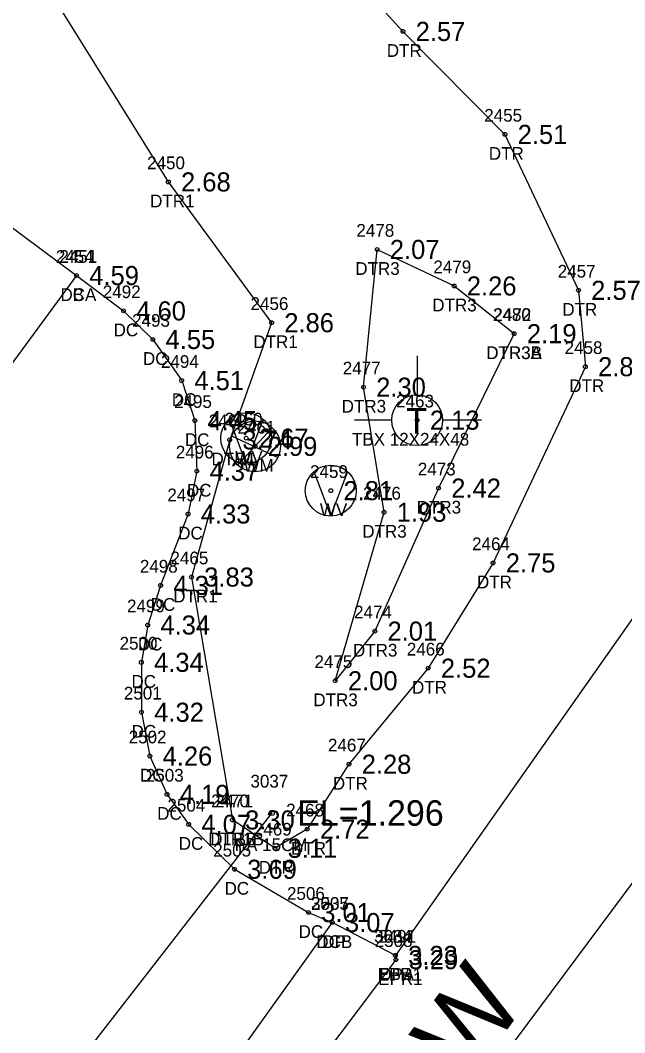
# Model space of a CAD drawing. Extents: x 2608598 to 2610682, y 641451 to 643526.
# Drawn here: x 2610013.4 to 2610061, y 642071.3 to 642151 of the extents above; entities that cross this region are included whole.
import ezdxf

# ---------------------------------------------------------------- set-up
doc = ezdxf.new("R2010")
doc.units = 0
for name, color, linetype in [('RD_EX_Bldg', 7, 'Continuous'), ('RD_EX_Bldg_txCode', 7, 'Continuous'), ('RD_EX_Conc', 7, 'Continuous'), ('RD_EX_Conc_txCode', 7, 'Continuous'), ('RD_EX_DR_Pipe', 7, 'Continuous'), ('RD_EX_DR_Pipe_txCode', 7, 'Continuous'), ('RD_EX_Driveway', 7, 'Continuous'), ('RD_EX_Driveway_txCode', 7, 'Continuous'), ('RD_EX_H2O', 7, 'Continuous'), ('RD_EX_H2O_txCode', 7, 'Continuous'), ('RD_EX_Road', 7, 'Continuous'), ('RD_EX_Road_txCode', 7, 'Continuous'), ('RD_EX_TX_Bldg_ELEV', 7, 'Continuous'), ('RD_EX_TX_Conc_ELEV', 7, 'Continuous'), ('RD_EX_TX_Driveway_ELEV', 7, 'Continuous'), ('RD_EX_TX_H2O_ELEV', 7, 'Continuous'), ('RD_EX_TX_Road_ELEV', 7, 'Continuous'), ('RD_EX_TX_UT_ELEV', 7, 'Continuous'), ('RD_EX_UT', 7, 'Continuous'), ('RD_EX_UT_txCode', 7, 'Continuous'), ('RD_HC_Cl', 7, 'Continuous'), ('RD_HC_Data', 7, 'Continuous'), ('RD_SMD_Locator', 7, 'Continuous'), ('RD_TX_Pipe_ElevEX', 7, 'Continuous')]:
    doc.layers.add(name, color=color, linetype=linetype)

msp = doc.modelspace()

# ---------------------------------------------------------------- linework, layer by layer
at = {"layer": 'RD_EX_Bldg'}
msp.add_lwpolyline([(2609946.85, 642146.346), (2609965.057, 642170.243), (2610017.876, 642130.878), (2610000.016, 642106.607), (2609946.85, 642146.346)], dxfattribs=at)
at = {"layer": 'RD_EX_Conc'}
msp.add_lwpolyline([(2610017.876, 642130.878), (2610021.568, 642128.103), (2610023.872, 642125.855), (2610026.14, 642122.62), (2610027.17, 642119.471), (2610027.332, 642115.497), (2610026.643, 642112.13), (2610024.484, 642106.517), (2610023.47, 642103.398), (2610022.969, 642100.465), (2610022.98, 642096.539), (2610023.642, 642093.093), (2610024.991, 642090.082), (2610026.69, 642087.723), (2610030.29, 642084.192), (2610036.112, 642080.789), (2610037.979, 642080.001)], dxfattribs=at)
at = {"layer": 'RD_EX_DR_Pipe'}
msp.add_line((2610033.217, 642088.618), (2610007.781, 642055.878), dxfattribs=at)
at = {"layer": 'RD_EX_Driveway'}
msp.add_lwpolyline([(2610042.94, 642077.419), (2610037.979, 642080.001), (2610027.537, 642065.432), (2610017.895, 642052.738), (2610020.807, 642047.622)], dxfattribs=at)
at = {"layer": 'RD_EX_H2O'}
for points in [[(2610001.65, 642196.002), (2609997.03, 642194.999), (2609993.92, 642192.054), (2609993.228, 642189.364), (2610025.09, 642138.242), (2610033.208, 642127.171), (2610029.914, 642117.957), (2610026.911, 642107.171), (2610030.124, 642088.07)], [(2610001.65, 642196.002), (2610043.535, 642150.077), (2610051.557, 642141.98), (2610057.335, 642129.719), (2610057.877, 642123.713), (2610050.622, 642108.282), (2610045.517, 642100.001), (2610039.292, 642092.453), (2610036.006, 642087.343), (2610033.47, 642085.842), (2610030.124, 642088.07)], [(2610052.28, 642126.31), (2610046.334, 642114.164), (2610041.322, 642102.919), (2610038.209, 642099.016), (2610042.053, 642112.267), (2610040.434, 642122.103), (2610041.506, 642132.933), (2610047.558, 642130.062), (2610052.28, 642126.31)]]:
    msp.add_lwpolyline(points, dxfattribs=at)
at = {"layer": 'RD_EX_Road'}
msp.add_lwpolyline([(2610073.957, 642143.053), (2610073.967, 642133.893), (2610072.62, 642129.267), (2610072.125, 642123.733), (2610071.192, 642117.593), (2610042.94, 642077.419), (2610042.982, 642077.082), (2610020.807, 642047.622), (2610010.682, 642034.572), (2609995.36, 642013.506), (2609993.975, 642012.164), (2609992.649, 642010.593), (2609982.727, 641996.329), (2609971.725, 641982.02), (2609971.56, 641981.898), (2609965.999, 641974.618)], dxfattribs=at)
at = {"layer": 'RD_EX_UT'}
for p, q in [((2610044.652, 642124.576), (2610044.652, 642121.507)), ((2610031.213, 642116.1), (2610029.909, 642119.582)), ((2610031.213, 642116.1), (2610032.535, 642119.545)), ((2610030.548, 642115.988), (2610033.215, 642118.885)), ((2610039.721, 642119.522), (2610042.652, 642119.522)), ((2610046.652, 642119.522), (2610049.721, 642119.522)), ((2610030.066, 642118.284), (2610033.697, 642116.571)), ((2610037.861, 642111.972), (2610036.558, 642115.454)), ((2610037.861, 642111.972), (2610039.184, 642115.417))]:
    msp.add_line(p, q, dxfattribs=at)
for centre in [(2610044.652, 642119.507), (2610031.213, 642118.093), (2610031.9, 642117.447), (2610037.861, 642113.964)]:
    msp.add_circle(centre, 2, dxfattribs=at)
at = {"layer": 'RD_HC_Cl'}
msp.add_line((2610099.475, 642133.968), (2609975.324, 641967.39), dxfattribs=at)
at = {"layer": 'RD_SMD_Locator'}
for centre, radius in [((2610043.535, 642150.077), 0.15), ((2610051.557, 642141.98), 0.15), ((2610025.09, 642138.242), 0.15), ((2610041.506, 642132.933), 0.15), ((2610017.876, 642130.878), 0.15), ((2610017.876, 642130.878), 0.15), ((2610047.558, 642130.062), 0.15), ((2610057.335, 642129.719), 0.15), ((2610021.568, 642128.103), 0.15), ((2610033.208, 642127.171), 0.15), ((2610023.872, 642125.855), 0.15), ((2610052.28, 642126.31), 0.15), ((2610052.28, 642126.31), 0.15), ((2610057.877, 642123.713), 0.15), ((2610026.14, 642122.62), 0.15), ((2610040.434, 642122.103), 0.15), ((2610027.17, 642119.471), 0.15), ((2610044.652, 642119.507), 0.15), ((2610029.914, 642117.957), 0.15), ((2610031.213, 642118.093), 0.15), ((2610031.9, 642117.447), 0.15), ((2610027.332, 642115.497), 0.15), ((2610037.861, 642113.964), 0.15), ((2610046.334, 642114.164), 0.15), ((2610042.053, 642112.267), 0.15), ((2610026.643, 642112.13), 0.15), ((2610050.622, 642108.282), 0.15), ((2610026.911, 642107.171), 0.15), ((2610024.484, 642106.517), 0.15), ((2610023.47, 642103.398), 0.15), ((2610041.322, 642102.919), 0.15), ((2610022.969, 642100.465), 0.15), ((2610045.517, 642100.001), 0.15), ((2610038.209, 642099.016), 0.15), ((2610022.98, 642096.539), 0.15), ((2610023.642, 642093.093), 0.15), ((2610039.292, 642092.453), 0.15), ((2610024.991, 642090.082), 0.15), ((2610033.217, 642088.618), 0.2), ((2610026.69, 642087.723), 0.15), ((2610030.124, 642088.07), 0.15), ((2610030.124, 642088.07), 0.15), ((2610036.006, 642087.343), 0.15), ((2610033.47, 642085.842), 0.15), ((2610030.29, 642084.192), 0.15), ((2610036.112, 642080.789), 0.15), ((2610037.979, 642080.001), 0.15), ((2610037.979, 642080.001), 0.15), ((2610042.94, 642077.419), 0.15), ((2610042.94, 642077.419), 0.15), ((2610042.982, 642077.082), 0.15)]:
    msp.add_circle(centre, radius, dxfattribs=at)

# ---------------------------------------------------------------- texts
at = {"layer": 'RD_EX_Bldg_txCode'}
for s, p in [('2451', (2610016.529, 642131.878)), ('B', (2610017.568, 642128.878))]:
    msp.add_text(s, height=1, dxfattribs=at).set_placement(p)
at = {"layer": 'RD_EX_Conc_txCode'}
for s, p in [('2454', (2610016.246, 642131.878)), ('DCA', (2610016.608, 642128.878)), ('2492', (2610019.938, 642129.103)), ('2493', (2610022.242, 642126.855)), ('DC', (2610020.788, 642126.103)), ('DC', (2610023.093, 642123.855)), ('2494', (2610024.51, 642123.62)), ('DC', (2610025.361, 642120.62)), ('2495', (2610025.54, 642120.471)), ('DC', (2610026.391, 642117.471)), ('2496', (2610025.679, 642116.497)), ('2497', (2610025.013, 642113.13)), ('DC', (2610026.553, 642113.497)), ('DC', (2610025.864, 642110.13)), ('2498', (2610022.854, 642107.517)), ('2499', (2610021.84, 642104.398)), ('DC', (2610023.705, 642104.517)), ('2500', (2610021.261, 642101.465)), ('DC', (2610022.691, 642101.398)), ('DC', (2610022.19, 642098.465)), ('2501', (2610021.594, 642097.539)), ('2502', (2610021.973, 642094.093)), ('DC', (2610022.2, 642094.539)), ('DC', (2610022.863, 642091.093)), ('2503', (2610023.322, 642091.082)), ('2504', (2610025.021, 642088.723)), ('DC', (2610024.212, 642088.082)), ('DC', (2610025.911, 642085.723)), ('2505', (2610028.621, 642085.192)), ('DC', (2610029.51, 642082.192)), ('2506', (2610034.419, 642081.789)), ('2507', (2610036.31, 642081.001)), ('DC', (2610035.333, 642078.789)), ('DCB', (2610036.727, 642078.001))]:
    msp.add_text(s, height=1, dxfattribs=at).set_placement(p)
at = {"layer": 'RD_EX_DR_Pipe_txCode'}
for s, p in [('3037', (2610031.548, 642090.618)), ('PA 15CM', (2610030.312, 642085.618))]:
    msp.add_text(s, height=1, dxfattribs=at).set_placement(p)
at = {"layer": 'RD_EX_Driveway_txCode'}
for s, p in [('3035', (2610036.31, 642081.001)), ('DP', (2610037.2, 642078.001)), ('3034', (2610041.271, 642078.419)), ('DPA', (2610041.673, 642075.419))]:
    msp.add_text(s, height=1, dxfattribs=at).set_placement(p)
at = {"layer": 'RD_EX_H2O_txCode'}
for s, p in [('DTR', (2610042.267, 642148.077)), ('2455', (2610049.927, 642142.98)), ('2450', (2610023.421, 642139.242)), ('DTR', (2610050.289, 642139.98)), ('DTR1', (2610023.657, 642136.242)), ('2478', (2610039.876, 642133.933)), ('DTR3', (2610039.789, 642130.933)), ('2479', (2610045.928, 642131.062)), ('2457', (2610055.705, 642130.719)), ('2456', (2610031.554, 642128.171)), ('DTR3', (2610045.841, 642128.062)), ('2480', (2610050.611, 642127.31)), ('2472', (2610050.65, 642127.31)), ('DTR', (2610056.067, 642127.719)), ('DTR1', (2610031.775, 642125.171)), ('DTR3A', (2610050.076, 642124.31)), ('DTR3B', (2610050.091, 642124.31)), ('2458', (2610056.247, 642124.713)), ('2477', (2610038.804, 642123.103)), ('DTR', (2610056.609, 642121.713)), ('DTR3', (2610038.718, 642120.103)), ('2462', (2610028.261, 642118.957)), ('DTR1', (2610028.481, 642115.957)), ('2473', (2610044.704, 642115.164)), ('2476', (2610040.4, 642113.267)), ('DTR3', (2610044.618, 642112.164)), ('DTR3', (2610040.337, 642110.267)), ('2464', (2610048.969, 642109.282)), ('2465', (2610025.258, 642108.171)), ('DTR', (2610049.355, 642106.282)), ('DTR1', (2610025.478, 642105.171)), ('2474', (2610039.692, 642103.919)), ('2466', (2610043.84, 642101.001)), ('DTR3', (2610039.606, 642100.919)), ('2475', (2610036.579, 642100.016)), ('DTR', (2610044.249, 642098.001)), ('DTR3', (2610036.492, 642097.016)), ('2467', (2610037.639, 642093.453)), ('DTR', (2610038.025, 642090.453)), ('2470', (2610028.455, 642089.07)), ('2471', (2610028.777, 642089.07)), ('2468', (2610034.352, 642088.343)), ('2469', (2610031.816, 642086.842)), ('DTR1B', (2610028.218, 642086.07)), ('DTRB', (2610028.384, 642086.07)), ('DTR', (2610034.738, 642085.343)), ('DTR', (2610032.202, 642083.842))]:
    msp.add_text(s, height=1, dxfattribs=at).set_placement(p)
at = {"layer": 'RD_EX_Road_txCode'}
for s, p in [('2508', (2610041.313, 642078.082)), ('2491', (2610041.594, 642078.419)), ('EPR1', (2610041.547, 642075.419)), ('EPR1', (2610041.589, 642075.082))]:
    msp.add_text(s, height=1, dxfattribs=at).set_placement(p)
at = {"layer": 'RD_EX_TX_Bldg_ELEV'}
msp.add_text('4.59', height=1.5, dxfattribs=at).set_placement((2610018.876, 642130.128))
at = {"layer": 'RD_EX_TX_Conc_ELEV'}
for s, p in [('4.59', (2610018.876, 642130.128)), ('4.60', (2610022.568, 642127.353)), ('4.55', (2610024.872, 642125.105)), ('4.51', (2610027.14, 642121.87)), ('4.45', (2610028.17, 642118.721)), ('4.37', (2610028.332, 642114.747)), ('4.33', (2610027.643, 642111.38)), ('4.31', (2610025.484, 642105.767)), ('4.34', (2610024.47, 642102.648)), ('4.34', (2610023.969, 642099.715)), ('4.32', (2610023.98, 642095.789)), ('4.26', (2610024.642, 642092.343)), ('4.19', (2610025.991, 642089.332)), ('4.07', (2610027.69, 642086.973)), ('3.69', (2610031.29, 642083.442)), ('3.01', (2610037.112, 642080.039)), ('3.07', (2610038.979, 642079.251))]:
    msp.add_text(s, height=1.5, dxfattribs=at).set_placement(p)
at = {"layer": 'RD_EX_TX_Driveway_ELEV'}
for s, p in [('3.07', (2610038.979, 642079.251)), ('3.23', (2610043.94, 642076.669))]:
    msp.add_text(s, height=1.5, dxfattribs=at).set_placement(p)
at = {"layer": 'RD_EX_TX_H2O_ELEV'}
for s, p in [('2.57', (2610044.535, 642149.327)), ('2.51', (2610052.557, 642141.23)), ('2.68', (2610026.09, 642137.492)), ('2.07', (2610042.506, 642132.183)), ('2.26', (2610048.558, 642129.312)), ('2.57', (2610058.335, 642128.969)), ('2.86', (2610034.208, 642126.421)), ('2.19', (2610053.28, 642125.56)), ('2.19', (2610053.28, 642125.56)), ('2.82', (2610058.877, 642122.963)), ('2.30', (2610041.434, 642121.353)), ('3.74', (2610030.914, 642117.207)), ('2.42', (2610047.334, 642113.414)), ('1.93', (2610043.053, 642111.517)), ('2.75', (2610051.622, 642107.532)), ('3.83', (2610027.911, 642106.421)), ('2.01', (2610042.322, 642102.169)), ('2.52', (2610046.517, 642099.251)), ('2.00', (2610039.209, 642098.266)), ('2.28', (2610040.292, 642091.703)), ('3.30', (2610031.124, 642087.32)), ('3.30', (2610031.124, 642087.32)), ('2.72', (2610037.006, 642086.593)), ('3.11', (2610034.47, 642085.092))]:
    msp.add_text(s, height=1.5, dxfattribs=at).set_placement(p)
at = {"layer": 'RD_EX_TX_Road_ELEV'}
for s, p in [('3.23', (2610043.94, 642076.669)), ('3.29', (2610043.982, 642076.332))]:
    msp.add_text(s, height=1.5, dxfattribs=at).set_placement(p)
at = {"layer": 'RD_EX_TX_UT_ELEV'}
for s, p in [('2.13', (2610045.652, 642118.757)), ('2.67', (2610032.213, 642117.343)), ('2.99', (2610032.9, 642116.697)), ('2.81', (2610038.861, 642113.214))]:
    msp.add_text(s, height=1.5, dxfattribs=at).set_placement(p)
at = {"layer": 'RD_EX_UT'}
msp.add_text('T', height=2, dxfattribs=at).set_placement((2610043.803, 642118.459))
at = {"layer": 'RD_EX_UT_txCode'}
for s, p in [('2463', (2610042.998, 642120.507)), ('2460', (2610029.52, 642119.093)), ('2461', (2610030.53, 642118.447)), ('TBX 12X24X48', (2610039.526, 642117.507)), ('WV', (2610030.354, 642116.093)), ('WM', (2610030.994, 642115.447)), ('2459', (2610036.231, 642114.964)), ('WV', (2610037.003, 642111.964))]:
    msp.add_text(s, height=1, dxfattribs=at).set_placement(p)
at = {"layer": 'RD_HC_Data'}
msp.add_text('S 36%%d 41\' 50" W', height=6, rotation=53.30287, dxfattribs=at).set_placement((2610019.672, 642028.568))
at = {"layer": 'RD_TX_Pipe_ElevEX'}
msp.add_text('EL=1.296', height=2, dxfattribs=at).set_placement((2610035.217, 642087.618))

doc.saveas('drawing.dxf')
